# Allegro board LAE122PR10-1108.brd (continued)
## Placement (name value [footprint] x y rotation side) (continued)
PC939  -  [C_0402]  59.18 57.03 180 bottom
PC940  -  [C_0603]  40.54 70.18 90 top
PC941  -  [C_0603]  52.41 65.1 90 top
PC942  -  [C_0402]  59.16 56.14 180 bottom
PC943  -  [C_0402]  56.12 54.35 90 bottom
PC944  -  [C_0402]  54.75 52.14 0 bottom
PC945  -  [C_0402]  60.48 54.93 90 bottom
PC946  -  [C_0402]  58.95 54.35 90 bottom
PC947  -  [C_0402]  57.01 54.35 90 bottom
PC949  -  [C_0402]  45.19 56.46 180 bottom
PC950  -  [C_0402]  58.06 55.27 270 bottom
PC951  -  [C_B2]  50.21 78.18 180 bottom
PC1001  -  [C_0603]  109.43 99.96 90 top
PC1002  -  [C_0603]  110.7 99.96 90 top
PC1003  -  [C_0603]  108.16 106.18 270 top
PC1004  -  [C_0603]  109.43 103.77 270 top
PC1005  -  [C_0603]  73.81 110.82 90 bottom
PC1006  -  [C_0603]  83.02 105.74 270 bottom
PC1007  -  [C_0603]  111.97 106.18 270 top
PC1008  -  [C_0603]  73.81 110.82 90 top
PC1009  -  [C_0603]  83.02 108.6 270 bottom
PC1010  -  [C_0603]  81.81 108.6 270 bottom
PC1011  -  [C_0603]  87.84 105.74 270 top
PC1012  -  [C_0603]  75.02 110.82 90 top
PC1013  -  [C_0603]  84.22 105.74 270 top
PC1014  -  [C_0603]  100.49 106.75 270 top
PC1015  -  [C_0603]  101.69 106.75 270 top
PC1016  -  [C_0603]  102.89 106.75 270 top
PC1017  -  [C_0603]  104.08 106.75 270 top
PC1018  -  [C_0603]  105.27 106.75 270 top
PC1019  -  [C_0603]  100.47 104.26 270 top
PC1020  -  [C_0603]  101.67 104.26 270 top
PC1021  -  [C_0603]  102.86 104.26 270 top
PC1022  -  [C_0603]  104.05 104.26 270 top
PC1023  -  [C_0603]  105.25 104.26 270 top
PC1024  -  [C_0603]  99.08 101.61 270 top
PC1025  -  [C_0603]  100.35 101.61 270 top
PC1026  -  [C_0603]  101.62 101.61 270 top
PC1027  -  [C_0603]  102.89 101.61 270 top
PC1028  -  [C_0603]  104.16 101.61 270 top
PC1029  -  [C_0603]  105.43 101.61 270 top
PC1030  -  [C_0201]  114.44 106.36 0 top
PC1031  -  [C_0201]  107.2 103.82 180 top
PC1032  -  [C_0201]  114.44 102.86 0 top
PC1033  -  [C_0201]  114.44 103.44 0 top
PC1034  -  [C_0201]  114.44 104.02 0 top
PC1035  -  [C_0201]  114.44 104.61 0 top
PC1036  -  [C_0201]  114.44 105.19 0 top
PC1037  -  [C_0201]  114.44 105.78 0 top
PC1038  -  [C_0201]  107.2 102.65 180 top
PC1039  -  [C_0201]  107.2 103.24 180 top
PC1040  -  [C_0201]  98.54 109 0 top
PC1041  -  [C_0201]  104.03 108.91 0 top
PC1042  -  [C_0201]  101.5 108.62 180 top
PC1043  -  [C_0201]  94.65 101.59 180 top
PC1044  -  [C_0201]  96.33 108.21 180 top
PC1045  -  [C_0201]  99.53 106.86 270 top
PC1046  -  [C_0201]  98.96 106.86 270 top
PC1047  -  [C_0201]  97.46 99.52 0 top
PC1048  -  [C_0201]  99.58 104.46 90 top
PC1049  -  [C_0201]  98.97 104.46 90 top
PC1050  -  [C_0201]  114.49 109.08 180 top
PC1051  -  [C_0201]  112.7 108.98 0 top
PC1052  -  [C_0201]  110.87 108.98 180 top
PC1053  -  [C_0201]  109.08 108.98 0 top
PC1054  -  [C_0201]  114.44 106.94 0 top
PC1055  -  [C_0201]  99.56 103.83 270 top
PC1056  -  [C_0201]  98.95 103.85 270 top
PC1057  -  [C_0603]  118.04 99.81 180 top
PC1058  -  [C_0603]  119.01 99.81 0 top
PC1059  -  [C_0603]  117.22 107.1 180 top
PC1060  -  [C_0603]  117.75 104.63 90 top
PC1061  -  [C_0603]  76.22 110.82 90 bottom
PC1062  -  [C_D3]  73.58 107.07 180 top
PC1063  -  [C_D3]  73.3 95.01 270 top
PC1064  -  [C_0603]  89.05 105.74 270 top
PC1065  -  [C_0603]  108.16 103.77 270 top
PC1066  -  [C_0603]  113.24 103.77 270 top
PC1067  -  [C_0603]  110.7 106.18 270 top
PC1068  -  [C_0603]  111.97 103.77 270 top
PC1069  -  [C_0603]  80.61 105.74 270 bottom
PC1070  -  [C_0603]  81.81 105.74 270 bottom
PC1071  -  [C_0603]  80.61 108.6 270 bottom
PC1072  -  [C_0603]  85.43 105.74 270 top
PC1073  -  [C_0603]  110.7 103.77 270 top
PC1074  -  [C_0603]  75.02 110.82 90 bottom
PC1075  -  [C_0603]  86.64 105.74 270 top
PC1076  -  [C_0603]  111.97 99.96 90 top
PC1077  -  [C_0603]  113.24 106.18 270 top
PC1078  -  [C_0603]  109.43 106.18 270 top
PC1079  -  [C_0603]  84.22 105.74 270 bottom
PC1080  -  [C_0603]  108.16 98.82 180 top
PC1081  -  [C_0603]  108.16 99.96 90 top
PC1082  -  [C_0603]  113.24 99.96 90 top
PC1083  -  [C_0201]  107.2 108.49 180 top
PC1084  -  [C_0201]  111.49 108.98 0 top
PC1085  -  [C_0201]  111.39 110.12 0 top
PC1086  -  [C_0201]  107.2 107.91 180 top
PC1087  -  [C_0201]  107.2 107.33 180 top
PC1088  -  [C_0201]  107.2 106.74 180 top
PC1089  -  [C_0201]  107.2 106.16 180 top
PC1090  -  [C_0201]  107.2 105.57 180 top
PC1091  -  [C_0201]  107.2 104.99 180 top
PC1092  -  [C_0201]  107.2 104.4 180 top
PC1093  -  [C_0201]  114.44 102.27 0 top
PC1094  -  [C_0201]  114.44 101.69 0 top
PC1095  -  [C_0201]  114.44 101.1 0 top
PC1096  -  [C_0201]  114.44 100.52 0 top
PC1097  -  [C_0201]  107.2 100.32 180 top
PC1098  -  [C_0201]  107.2 99.73 180 top
PC1099  -  [C_0201]  107.2 101.48 180 top
PC1125  -  [C_0201]  107.2 100.9 180 top
PC1126  -  [C_0201]  107.2 102.07 180 top
PC1127  -  [C_D2]  74.51 108.3 270 bottom
PC1128  -  [C_D2]  74.51 98.27 270 bottom
PC1129  -  [C_0603]  90.32 99.39 270 top
PC1130  -  [C_0603]  90.32 102.18 270 top
PC1131  -  [C_0603]  89.11 102.18 270 top
PC1132  -  [C_0603]  89.11 99.39 270 top
PC1133  -  [C_0603]  87.91 102.18 270 top
PC1134  -  [C_0603]  87.91 99.39 270 top
PC1135  -  [C_0603]  86.7 102.18 270 top
PC1136  -  [C_0603]  86.7 99.39 270 top
PC1137  -  [C_0603]  85.49 102.18 270 top
PC1138  -  [C_0603]  85.49 99.39 270 top
PC1139  -  [C_0603]  117.4 103.55 180 top
PC1140  -  [C_0603]  76.76 118.78 90 top
PC1141  -  [C_0603]  74.34 118.78 90 top
PC1142  -  [C_0603]  76.21 118.78 90 bottom
PC1143  -  [C_0603]  73.14 118.78 90 top
PC1144  -  [C_0603]  75 118.78 90 bottom
PC1145  -  [C_0603]  75.55 118.78 90 top
PC1146  -  [C_0603]  73.8 118.78 90 bottom
PC1147  -  [C_0201]  116.31 110.17 180 top
PC1148  -  [C_0201]  118.51 107.82 0 top
PC1149  -  [C_0201]  116.39 106.01 180 top
PC1150  -  [C_0201]  116.39 105.44 180 top
PC1151  -  [C_0201]  116.39 104.87 180 top
PC1152  -  [C_0201]  118.48 103.49 0 top
PC1153  -  [C_0201]  118.48 102.91 0 top
PC1164  -  [C_0201]  114.44 107.53 0 top
PC1170  -  [C_0603]  85.43 105.74 270 bottom
PC1171  -  [C_0603]  86.64 105.74 270 bottom
PC1172  -  [C_0603]  84.22 108.6 270 bottom
PC1173  -  [C_0603]  85.43 108.6 270 bottom
PC1174  -  [C_0603]  86.64 108.6 270 bottom
PC1175  -  [C_0603]  81.75 99.39 270 bottom
PC1176  -  [C_0603]  83.02 102.18 270 bottom
PC1177  -  [C_0603]  81.75 102.18 270 bottom
PC1178  -  [C_0603]  83.02 99.39 270 bottom
PC1179  -  [C_0603]  84.29 99.39 270 top
PC1180  -  [C_0603]  84.29 102.18 270 top
PC1181  -  [C_0603]  97.12 97.61 0 top
PC1201  -  [C_0402]  36.47 58.7 270 bottom
PC1202  -  [C_0603]  46.84 103.58 270 top
PC1203  -  [C_0402]  47.46 109.62 270 top
PC1204  -  [C_0402]  35.06 63.7 0 bottom
PC1205  -  [C_0402]  39.66 53.35 180 top
PC1206  -  [C_0402]  40.97 55.13 0 top
PC1207  -  [C_0402]  41.87 56.92 270 top
PC1208  -  [C_0402]  22.87 113.17 0 top
PC1210  -  [C_0402]  31.14 120.93 270 top
PC1211  -  [C_0402]  36.59 55.13 0 top
PC1212  -  [C_0402]  36.59 56.91 0 top
PC1213  -  [C_0402]  35.14 56.7 90 top
PC1214  -  [C_0402]  28.03 124.2 90 top
PC1216  -  [C_0402]  26.07 113.17 180 top
PC1217  -  [C_0402]  248.94 97.22 90 top
PC1286  -  [C_0402]  51.48 60.15 180 top
PD1  -  [TVNST52302AB0_SOT523-3]  166.79 64.51 45 top
PD2  -  [TVNST52302AB0_SOT523-3]  165.33 63.05 45 top
PD3  -  [DB3J315E0L_SMINI3-F2-B3]  285.9 11.88 0 top
PD4  -  [PESD5V0U2BT_SOT23-3]  39.65 127.16 180 top
PD5  -  [PDS5100H-13_POWERDI5-3]  51.08 114.01 90 bottom
PD100  -  [RB520SM-30T2R_EMD2-2]  185.44 60.88 180 bottom
PD901  -  [SDMK0340L-7-F_SOD323-2]  48.91 57.54 180 bottom
PD903  -  [RB520SM-30T2R_EMD2-2]  48.91 59.26 180 bottom
PD904  -  [SDMK0340L-7-F_SOD323-2]  48.91 60.97 180 bottom
PD905  -  [BAT54CW_SOT323-3]  42.51 57.61 0 bottom
PD1202  -  [PDS5100H-13_POWERDI5-3]  49.36 107.63 270 bottom
PD1205  -  [SDMK0340L-7-F_SOD323-2]  35.14 54.25 90 bottom
PD1801  -  [BAT54CW_SOT323-3]  37.55 58.3 270 bottom
PH601  -  [R_0402]  58.77 94.5 180 bottom
PH602  -  [R_0402]  67.35 94.63 180 bottom
PH603  -  [R_0402]  57.29 111.71 0 bottom
PH604  -  [R_0402]  72.68 119.64 270 bottom
PH605  -  [R_0402]  66.43 103.13 0 bottom
PJP1  -  [JUMP_43X39]  125.87 124.03 0 top
PJP2  -  [JUMP_43X39]  121.8 123.9 0 top
PJP3  -  [JUMP_43X118]  138.96 122.73 270 bottom
PJP4  -  [JUMP_43X39]  145.96 83.13 180 top
PJP7  -  [JUMP_43X39]  36.16 88.23 270 top
PJP8  -  [JUMP_43X118]  21.44 76.21 0 bottom
PJP13  -  [JUMP_43X39]  65.04 127.2 0 top
PJP14  -  [JUMP_43X79]  271.76 73.35 0 top
PJP15  -  [JUMP_43X39]  247.99 67.4 270 top
PJP16  -  [JUMP_43X39]  246.21 60.16 270 top
PJP17  -  [JUMP_43X79]  243.17 59.68 270 top
PJP18  -  [JUMP_43X39]  245.77 66.48 90 top
PJP19  -  [JUMP_43X39]  265.89 57.54 0 top
PJP20  -  [JUMP_43X39]  262.37 87.12 90 top
PJP21  -  [JUMP_43X39]  259.99 87.12 90 top
PJP22  -  [JUMP_43X39]  251.46 76.13 90 top
PJP31  -  [JUMP_43X118]  27.27 49.25 90 bottom
PJP35  -  [JUMP_43X39]  206.58 56.4 0 top
PJP36  -  [JUMP_43X79]  249.39 108.38 270 top
PJP37  -  [JUMP_43X39]  248.7 113.36 180 top
PJP38  -  [JUMP_43X39]  149.68 65.42 180 top
PJP39  -  [JUMP_43X118]  153 65.31 90 top
PJP40  -  [JUMP_43X79]  276.1 86.05 180 top
PJP41  -  [JUMP_43X118]  276.67 95.9 180 top
PJP42  -  [JUMP_43X39]  211.59 51.45 0 top
PJP100  -  [JUMP_43X79]  152.49 67.34 90 bottom
PJP101  -  [JUMP_43X79]  182.9 50.77 90 bottom
PJP102  -  [JUMP_43X118]  167.73 72.19 270 bottom
PJP103  -  [JUMP_43X118]  198.67 55.95 0 top
PJP200  -  [JUMP_43X118]  71.8 58.43 0 top
PJP201  -  [JUMP_43X39]  70.81 70.89 0 top
PJP202  -  [JUMP_43X79]  63.48 75.19 0 top
PJP301  -  [JUMP_43X79]  147.98 82.62 90 bottom
PJP302  -  [JUMP_43X118]  160.4 87.86 180 bottom
PJP391  -  [JUMP_43X39]  152.17 109.5 0 bottom
PJP401  -  [JUMP_43X79]  137.25 128.2 270 bottom
PJP402  -  [JUMP_43X79]  149.25 125.72 270 bottom
PJP403  -  [JUMP_43X39]  145.79 128.53 180 bottom
PJP404  -  [JUMP_43X39]  161.82 127.11 180 bottom
PJP501  -  [JUMP_43X39]  168.19 68.46 315 bottom
PJP502  -  [JUMP_43X39]  177.63 61.48 315 bottom
PJP505  -  [JUMP_43X39]  153.9 57.61 180 top
PJP506  -  [JUMP_43X39]  146.66 62.43 180 top
PJP601  -  [JUMP_43X118]  61.43 82.86 270 bottom
PJP602  -  [JUMP_43X79]  65.05 88.19 270 top
PJP603  -  [JUMP_43X39]  64.22 113.31 270 bottom
PJP901  -  [JUMP_43X118-NPM]  49.6 83.01 180 bottom
PJP1202  -  [JUMP_43X118]  29.45 115.45 0 top
PJPDC1  -  [CVILU_CI0805M1HRC-NH_5P-T]  38 122.55 270 bottom
PL1  -  [TAIYO_FBMJ4516HS720NT_2P]  171.16 54.93 90 top
PL2  -  [TAIYO_FBMJ4516HS720NT_2P]  173.44 54.93 90 top
PL3  -  [MURAT_BLM15AG102SN1D_2P]  37.93 123.35 0 top
PL4  -  [TAIYO_FBMJ4516HS720NT_2P]  41.23 120.79 0 bottom
PL100  -  [CYNTE_PCMC063T-1R5MN_2P]  158.77 76.59 0 bottom
PL101  -  [CYNTE_PCMC063T-1R5MN_2P]  189.26 55.25 0 bottom
PL201  -  [CYNTE_PCMB063T-1R0MS_2P]  67.4 65.91 270 bottom
PL301  -  [MAG_MMD-05CZ-R68M-X2L_2P]  159.2 82.69 0 bottom
PL402  -  [MAG_MLV-FY12N1R0M-O1L_2P]  138.55 130.76 180 bottom
PL404  -  [MAG_MLV-FY12N1R0M-O1L_2P]  154.42 127.96 180 bottom
PL501  -  [MAG_MLV-FY12N1R0M-O1L_2P]  174.17 63.73 315 bottom
PL602  -  [9A_Z80_1812_2P-NPM]  61.43 84.21 270 bottom
PL610  -  [MAG_MMD06CZER15MG_4P]  69.94 107.39 180 bottom
PL612  -  [MAG_MMD06CZER15MG_4P]  70.25 98.88 180 bottom
PL614  -  [MAG_MMD05CZR47M_4P]  75.21 115.5 180 bottom
PL901  -  [MAGLA_MMD-05CZ-1R0M-M7L_2P]  47 83.01 0 bottom
PL902  -  [CYNTE_PCMB103T-2R2MS_2P]  44.19 68.02 0 bottom
PL1201  -  [5A_Z120_0805_2P]  23.53 116.22 0 top
PL1202  -  [5A_Z120_0805_2P]  23.53 114.56 0 top
PQ1  -  [DMN65D8LDW-7_SOT363-6]  55.39 112.33 90 top
PQ2  -  [FDV301N-G_SOT23-3]  37.2 121.91 90 top
PQ3  -  [MMST3904-7-F_SOT323-3]  35.46 124.92 0 top
PQ4  -  [FDMC6679AZ_MLP8-5]  47.73 112.05 180 bottom
PQ5  -  [NTR4502PT1G_SOT23-3]  48.51 113.74 270 top
PQ6  -  [DMN65D8LW-7_SOT323-3]  49.68 120.47 270 bottom
PQ7  -  [DMN65D8LW-7_SOT323-3]  44.03 111.87 90 bottom
PQ8  -  [DMN65D8LW-7_SOT323-3]  59.14 119.84 270 bottom
PQ9  -  [FDMC6679AZ_MLP8-5]  45.78 118.76 0 bottom
PQ501  -  [AON7934_DFN3X3A8-10]  68.05 113.57 180 bottom
PQ904  -  [AON6970_DFN5X6D-8-7]  59.88 65.42 90 top
PQ905  -  [AON6992_DFN5X6D-8-7]  47.78 71.49 90 top
PQ906  -  [AON7409_DFN8-5]  175.56 54.14 0 top
PQ909  -  [DMN65D8LW-7_SOT323-3]  51.2 54.31 0 bottom
PQ1201  -  [DMN65D8LDW-7_SOT363-6]  46.44 106.29 90 top
PQ1202  -  [FDMC6679AZ_MLP8-5]  51.61 109.55 180 top
PQ1203  -  [NTR4502PT1G_SOT23-3]  44.54 105.14 180 bottom
PQ1204  -  [DMN65D8LDW-7_SOT363-6]  40.59 107.01 0 bottom
PQ1205  -  [DMN65D8LW-7_SOT323-3]  40.73 63.7 180 bottom
PQ1206  -  [FDMC6679AZ_MLP8-5]  30.06 119.05 90 top
PQ1207  -  [DMN66D0LDW-7_SOT363-6]  44.29 50.48 90 bottom
PQ1208  -  [DMN66D0LDW-7_SOT363-6]  41.02 50.48 90 bottom
PQ1209  -  [DMN65D8LDW-7_SOT363-6]  30.95 123.57 90 top
PQ1210  -  [DMN66D0LDW-7_SOT363-6]  52.66 51.78 270 bottom
PQ1211  -  [DMN66D0LDW-7_SOT363-6]  49.42 51.78 270 bottom
PQ1212  -  [DMN65D8LW-7_SOT323-3]  33.7 58.13 0 bottom
PQ1213  -  [FDMC6679AZ_MLP8-5]  48.53 105.19 270 top
PQ1214  -  [DMN65D8LDW-7_SOT363-6]  44.69 101.02 270 top
PQ1215  -  [NTR4502PT1G_SOT23-3]  46.46 101.71 270 bottom
PQ1216  -  [DMN65D8LW-7_SOT323-3]  59.68 51.32 270 bottom
PR1  -  [R_0402]  168.17 65.23 315 top
PR2  -  [R_0402]  283.93 9.9 90 top
PR3  -  [R_0402]  42.31 120.61 270 top
PR4  -  [R_0402]  44.09 120.61 270 top
PR5  -  [R_0402]  43.2 119.7 90 top
PR6  -  [R_0402]  37.17 125.63 270 top
PR7  -  [R_0402]  33.74 126.2 270 top
PR8  -  [R_0402]  37.17 127.4 270 top
PR10  -  [R_0402]  52.35 114.96 270 top
PR11  -  [R_0402]  46.33 109.8 180 bottom
PR12  -  [R_0402]  46.62 121.55 0 bottom
PR13  -  [R_0805]  43.78 118.97 270 bottom
PR14  -  [R_0402]  44.42 116.03 180 bottom
PR15  -  [R_0402]  52.35 113.12 270 top
PR16  -  [R_0402]  44.41 109.79 90 bottom
PR17  -  [R_0402]  55.19 114.76 0 top
PR18  -  [R_0402]  48.4 121.55 0 bottom
PR19  -  [R0402_0OHM]  56.98 113.85 90 top
PR20  -  [R0402_0OHM]  42.07 110.06 180 bottom
PR21  -  [R0402_0OHM]  57.69 121.42 180 bottom
PR22  -  [R0402_0OHM]  57.69 120.53 180 bottom
PR23  -  [R0402_0OHM]  52.73 120.14 90 bottom
PR24  -  [R_0402]  41.04 111.44 90 bottom
PR25  -  [R0402_0OHM]  54.33 114.76 180 top
PR26  -  [R0402_0OHM]  60.15 118.82 0 top
PR27  -  [R_0402]  57.69 119.64 180 bottom
PR28  -  [R_0402]  61.06 119.71 180 top
PR29  -  [R0402_0OHM]  60.15 121.61 0 bottom
PR100  -  [R0603_0OHM]  156.36 72.53 270 bottom
PR102  -  [R_0402]  182.92 58.94 180 bottom
PR103  -  [R_0402]  182.92 59.83 180 bottom
PR104  -  [R0402_0OHM]  157.75 79.74 0 top
PR105  -  [R0402_0OHM]  157.75 78.85 0 top
PR106  -  [R_1206]  158.84 72.15 0 bottom
PR107  -  [R_0402]  180.82 57.59 180 bottom
PR108  -  [R_0402]  155.21 79.58 0 bottom
PR111  -  [R0603_0OHM]  186.4 52.27 270 bottom
PR112  -  [R_1206]  188.11 54.37 0 top
PR113  -  [R_0402]  181.7 57.61 270 bottom
PR114  -  [R0402_0OHM]  183.79 59.84 270 bottom
PR116  -  [R_0402]  152.55 78.8 90 bottom
PR117  -  [R_0402]  185.75 59.84 0 bottom
PR119  -  [R0402_0OHM]  179.03 57.61 270 bottom
PR120  -  [R0402_0OHM]  180.82 56.7 180 bottom
PR202  -  [R_1206]  67.65 66.37 90 top
PR203  -  [R0603_0OHM]  64.41 68.4 180 bottom
PR204  -  [R_0402]  63.96 71.7 0 top
PR205  -  [R_0402]  64.48 71.65 270 bottom
PR206  -  [R_0402]  64.87 72.59 180 top
PR207  -  [R_0402]  63.59 70.74 90 bottom
PR208  -  [R0402_0OHM]  70.9 74.13 180 top
PR209  -  [R_0402]  70.89 75 90 top
PR210  -  [R0402_0OHM]  72.68 74.13 180 top
PR212  -  [R_0402]  71.78 75 90 top
PR302  -  [R_0402]  156.11 86.17 90 bottom
PR303  -  [R_1206]  159.47 83.69 270 top
PR304  -  [R0603_0OHM]  156.42 83.83 0 top
PR306  -  [R_0402]  154.33 87.08 270 bottom
PR307  -  [R_0402]  157.1 86.19 180 top
PR308  -  [R_0402]  153.44 87.08 270 bottom
PR310  -  [R_0402]  156.18 87.04 90 top
PR311  -  [R_0402]  155.22 86.17 90 bottom
PR312  -  [R0402_0OHM]  157 86.17 90 bottom
PR402  -  [R0402_0OHM]  144.68 128.14 90 top
PR403  -  [R_0402]  143.72 128.14 90 top
PR404  -  [R_0402]  140.36 129.82 270 top
PR405  -  [R_0603]  138.52 131.52 270 top
PR406  -  [R0402_0OHM]  164.63 127.52 180 top
PR407  -  [R_0402]  163.71 126.63 0 top
PR408  -  [R_0402]  157 131.09 270 top
PR409  -  [R_0603]  154.33 128.66 270 top
PR410  -  [R_0402]  164.63 129.3 180 top
PR411  -  [R_0402]  159.93 132.09 180 bottom
PR412  -  [R_0402]  137.68 133.36 0 bottom
PR413  -  [R_0402]  143.99 133.74 180 bottom
PR414  -  [R_0402]  142.2 133.75 270 top
PR415  -  [R_0402]  143.08 132.85 0 bottom
PR416  -  [R_0402]  143.08 132.85 0 top
PR417  -  [R_0402]  159.03 133.88 270 bottom
PR418  -  [R_0402]  157.88 131.09 270 top
PR419  -  [R_0402]  159.02 131.2 0 bottom
PR420  -  [R_0402]  158.77 130.17 90 top
PR421  -  [R_0402]  139.52 132.66 0 bottom
PR422  -  [R_0402]  140.44 133.55 180 bottom
PR423  -  [R0402_0OHM]  156.37 132.09 180 bottom
PR424  -  [R_0402]  156.37 131.2 180 bottom
PR425  -  [R0402_0OHM]  140.35 128.03 0 top
PR426  -  [R0402_0OHM]  164.63 128.41 180 top
PR427  -  [R_0402]  142.21 132.85 180 bottom
PR428  -  [R_0402]  158.15 131.2 180 bottom
PR501  -  [R_0402]  172.91 68.27 135 bottom
PR502  -  [R_0603]  172.63 62.31 135 bottom
PR504  -  [R0402_0OHM]  174.55 68.19 225 bottom
PR505  -  [R_0402]  174.53 66.91 45 bottom
PR506  -  [R_0402]  172.28 70.16 225 bottom
PR513  -  [R0402_0OHM]  149.38 57.49 270 top
PR514  -  [R_0402]  151.15 56.58 90 top
PR515  -  [R_0402]  146.96 60.86 270 top
PR516  -  [R_0402]  146.06 59.07 0 top
PR517  -  [R_0402]  171.06 67.91 135 bottom
PR601  -  [R_0402]  44.99 93.74 180 bottom
PR602  -  [R0402_0OHM]  44.99 96.59 180 top
PR603  -  [R0402_0OHM]  44.99 97.48 180 top
PR604  -  [R_0402]  44.99 94.63 180 bottom
PR605  -  [R_0402]  44.99 95.51 180 bottom
PR606  -  [R0402_0OHM]  58.63 114.55 180 bottom
PR608  -  [R_0402]  47.06 95.45 0 bottom
PR610  -  [R_0402]  47.57 89.8 0 top
PR611  -  [R_0402]  47.27 97.24 270 bottom
PR612  -  [R_0402]  44.33 92.53 0 top
PR613  -  [R_0402]  46.51 92.04 270 bottom
PR614  -  [R0402_0OHM]  44.85 90.04 90 top
PR616  -  [R0402_0OHM]  45.74 90.04 90 top
PR617  -  [R_0402]  50.07 91.58 180 bottom
PR618  -  [R_0402]  44.46 93.42 0 top
PR619  -  [R_0603]  61.17 112.91 0 top
PR620  -  [R0402_0OHM]  46.63 88.9 90 top
PR621  -  [R_0402]  49.36 88.01 90 top
PR622  -  [R_0402]  50.27 89.8 180 top
PR623  -  [R_0402]  48.4 88.02 90 top
PR624  -  [R_0603]  71.4 115.71 180 top
PR625  -  [R0402_0OHM]  44.46 94.31 0 top
PR626  -  [R_0402]  44.46 95.2 0 top
PR627  -  [R_1206]  68.79 114.5 180 top
PR628  -  [R_0402]  67.33 97.5 270 top
PR629  -  [R_0402]  50.87 93.42 0 bottom
PR630  -  [R_0402]  49.12 97.23 180 bottom
PR631  -  [R_0402]  48.28 92.04 270 bottom
PR632  -  [R_0402]  53.82 88.85 180 top
PR633  -  [R_0402]  66.44 97.5 270 top
PR635  -  [R_0402]  54.51 91.88 90 top
PR636  -  [R_0402]  48.98 99.38 90 bottom
PR638  -  [R_0402]  53.82 89.74 180 top
PR639  -  [R_0402]  52.67 95.46 270 bottom
PR640  -  [R_0402]  55.38 97.23 0 top
PR641  -  [R_0402]  47.19 100.28 0 bottom
PR642  -  [R_0402]  71.73 118.73 90 bottom
PR643  -  [R_0402]  71.16 116.79 180 top
PR644  -  [R_0402]  55.38 98.12 0 top
PR645  -  [R_0402]  56.3 93.67 180 top
PR646  -  [R_0402]  50.76 99.38 90 bottom
PR647  -  [R_0402]  51.89 91.9 0 bottom
PR648  -  [R_0402]  54.51 94.58 270 top
PR649  -  [R_0402]  51.64 99.39 0 bottom
PR650  -  [R_0402]  55.38 92.78 0 top
PR651  -  [R_0402]  50.89 97.24 270 bottom
PR652  -  [R_0402]  49.87 99.38 90 bottom
PR656  -  [R_0402]  64.02 105.23 0 top
PR657  -  [R_0402]  64.65 103.13 0 bottom
PR659  -  [R0402_0OHM]  59.98 111.71 180 bottom
PR660  -  [R_0603]  52.22 109.42 0 bottom
PR661  -  [R_0603]  64.92 106.31 180 top
PR662  -  [R_0402]  55.13 111.71 0 bottom
PR663  -  [R_1206]  61.61 102.37 180 bottom
PR671  -  [R0402_0OHM]  59.6 95.51 180 bottom
PR672  -  [R_0603]  60.55 87.65 90 bottom
PR674  -  [R_0603]  65.3 97.48 90 top
PR676  -  [R_1206]  62.38 98.05 270 top
PR678  -  [R_0402]  47.08 93.66 90 bottom
PR679  -  [R0402_0OHM]  61 116.09 180 top
PR680  -  [R_0402]  59.26 90.88 0 top
PR901  -  [R_1206_4P-D]  48.27 83.28 0 top
PR909  -  [R_0402]  53.48 60.97 0 bottom
PR910  -  [R_0402]  53.48 61.86 0 bottom
PR914  -  [R0603_0OHM]  57.05 61.22 90 top
PR915  -  [R_0402]  60.91 59.26 0 top
PR916  -  [R_0805]  53.26 59.45 180 bottom
PR917  -  [R_1206_4P-D]  170.08 52.03 0 top
PR918  -  [R_0402]  52.98 56.58 90 bottom
PR919  -  [R_0402]  50.56 58.37 0 top
PR920  -  [R0402_0OHM]  50.56 57.48 0 top
PR921  -  [R_0603]  60.79 58.05 0 top
PR922  -  [R0402_0OHM]  50.56 56.59 0 top
PR923  -  [R_1206]  43.52 68.65 180 top
PR924  -  [R_1206]  55.71 63.57 180 top
PR925  -  [R_0402]  53.85 56.45 0 bottom
PR926  -  [R0402_0OHM]  50.56 55.7 0 top
PR927  -  [R_0402]  50.81 57.29 0 bottom
PR928  -  [R0402_0OHM]  52.98 55.71 270 bottom
PR929  -  [R0402_0OHM]  60.84 56.78 0 bottom
PR930  -  [R_0402]  53.85 55.56 0 bottom
PR931  -  [R_0402]  53.94 52.07 90 top
PR932  -  [R_0402]  55.71 52.98 270 top
PR933  -  [R_0402]  54.82 52.07 90 top
PR934  -  [R_0402]  55.66 53.03 180 bottom
PR935  -  [R0402_0OHM]  56.59 50.75 0 top
PR936  -  [R0402_0OHM]  57.49 52.98 270 top
PR937  -  [R_0402]  61.35 55.83 0 bottom
PR938  -  [R_0402]  61.35 54.94 0 bottom
PR939  -  [R0402_0OHM]  44.22 58.61 90 bottom
PR940  -  [R_0402]  58.38 52.07 90 top
PR941  -  [R0402_0OHM]  40.73 58.61 90 bottom
PR942  -  [R0402_0OHM]  48.26 54.75 180 bottom
PR943  -  [R0603_0OHM]  53.11 60.59 0 top
PR944  -  [R_0402]  51.5 62.14 180 top
PR945  -  [R_0402]  51.48 61.06 180 top
PR946  -  [R0402_0OHM]  43.27 54.1 90 bottom
PR947  -  [R0402_0OHM]  56.59 52.14 0 bottom
PR948  -  [R_0402]  57.61 53.03 0 bottom
PR949  -  [R0402_0OHM]  56.6 52.98 270 top
PR950  -  [R_0402]  45.11 59.52 270 bottom
PR951  -  [R0402_0OHM]  52.91 52.84 0 bottom
PR953  -  [R_0402]  43.46 56.16 270 top
PR960  -  [R0402_0OHM]  50.56 59.26 0 top
PR1201  -  [R_0402]  41.88 53.35 180 top
PR1202  -  [R_0402]  44.3 108.91 180 bottom
PR1203  -  [R_0402]  40.98 56.01 90 top
PR1205  -  [R_0402]  45.74 103.21 270 top
PR1206  -  [R_0402]  38.75 56.02 0 top
PR1207  -  [R_0402]  48.35 109.62 270 top
PR1208  -  [R_0402]  38.75 55.13 0 top
PR1209  -  [R_0402]  42.06 108.93 270 bottom
PR1210  -  [R_0402]  33.29 54.43 0 top
PR1211  -  [R0402_0OHM]  36.52 62.56 0 top
PR1212  -  [R_0402]  44.85 102.3 90 top
PR1213  -  [R_0402]  48.36 107.83 180 top
PR1214  -  [R_0402]  41.54 102.97 180 bottom
PR1215  -  [R0402_0OHM]  37.76 63.7 180 bottom
PR1216  -  [R0402_0OHM]  36.36 60.23 180 bottom
PR1217  -  [R_0402]  39.66 54.24 180 top
PR1218  -  [R0402_0OHM]  41.54 103.86 180 bottom
PR1219  -  [R_0402]  40.97 54.24 0 top
PR1220  -  [R0402_0OHM]  42.68 106.94 0 top
PR1221  -  [R0402_0OHM]  41.63 60.65 180 bottom
PR1222  -  [R_0402]  42.68 107.83 0 top
PR1223  -  [R0402_0OHM]  41.17 108.01 90 bottom
PR1224  -  [R_0402]  39.79 60.65 180 bottom
PR1225  -  [R0402_0OHM]  38.95 61.59 90 bottom
PR1226  -  [R_0402]  36.84 64.59 0 bottom
PR1227  -  [R_0402]  27.85 122.44 180 top
PR1228  -  [R_0402]  32.03 120.01 90 top
PR1229  -  [R_0402]  29.69 122.44 180 top
PR1230  -  [R_0402]  46.19 51.18 90 top
PR1231  -  [R_0402]  50.06 51.18 90 top
PR1232  -  [R_0402]  44.73 51.18 90 top
PR1233  -  [R_0402]  47.08 51.18 90 top
PR1234  -  [R_0402]  43.84 50.54 90 top
PR1235  -  [R_0402]  49.16 52.84 0 bottom
PR1236  -  [R_0402]  30.94 125.99 0 top
PR1237  -  [R_0402]  37.5 57.8 180 top
PR1238  -  [R0402_0OHM]  35.14 54.93 90 top
PR1239  -  [R_0402]  37.5 53.35 180 top
PR1240  -  [R_0402]  34.25 57.62 270 top
PR1241  -  [R0402_0OHM]  44.74 52.84 180 bottom
PR1242  -  [R0402_0OHM]  47.97 52.09 270 top
PR1243  -  [R0402_0OHM]  33.36 56.7 90 top
PR1244  -  [R0402_0OHM]  40.71 52.02 0 top
PR1245  -  [R0402_0OHM]  51.07 52.84 0 bottom
PR1246  -  [R_0402]  36.59 54.24 0 top
PR1247  -  [R_0402]  36.59 56.02 0 top
PR1248  -  [R_0402]  32.41 56.7 90 top
PR1249  -  [R_0402]  33.29 55.32 0 top
PR1250  -  [R0402_0OHM]  32.41 55.33 270 top
PR1251  -  [R_0402]  52.08 101.93 180 top
PR1252  -  [R_0402]  49.95 101.93 180 top
PR1253  -  [R_0402]  45.57 98.63 180 top
PR1254  -  [R_0402]  34.25 59.4 270 top
PR1255  -  [R_0402]  32.87 56.88 0 bottom
PR1257  -  [R0402_0OHM]  47.38 52.84 0 bottom
PR1258  -  [R_0402]  45.6 52.84 0 bottom
PR1259  -  [R_0402]  41.54 52.84 0 bottom
PR1260  -  [R_0402]  40.71 51.13 0 top
PR1261  -  [R_0402]  42.95 51.46 270 top
PRP1  -  [RP_0804_8P4R]  167.81 61.67 45 top
PT1  -  [TPC12]  32.41 58.57 0 top
PU1  -  [TC7SH08FU_SSOP5]  55.71 121.18 270 bottom
PU2  -  [AP2204RA-3P3TRG1_SOT89-3]  68.22 121.02 270 bottom
PU100  -  [SY8288BRAC_QFN20_3X3]  155.36 73.9 90 bottom
PU102  -  [SY8288CRAC_QFN20_3X3]  185.84 54.09 90 bottom
PU200  -  [SY8210AQVC_QFN19_4X3]  69.06 72.01 180 bottom
PU301  -  [SYX196DQNC_QFN10_3X3]  156.53 84.67 180 bottom
PU401  -  [SY8057QDC_QFN16_3X3]  140.08 129.05 0 bottom
PU402  -  [SY8057QDC_QFN16_3X3]  155.95 127.53 0 bottom
PU501  -  [RT8097ALGE_SOT23-6]  173.97 65.51 225 bottom
PU503  -  [AP7361C-FGE-7_U-DFN3030-8_3X3]  148.3 60.61 270 top
PU602  -  [ISL62883CHRTZ-T_TQFN40_5X5-S]  48.33 91.69 0 top
PU610  -  [CSD97374CQ4M_SON8_3P5X4P5]  58.61 110.32 270 bottom
PU612  -  [CSD97374CQ4M_SON8_3P5X4P5]  60.1 94.15 0 bottom
PU614  -  [ISL95808HRZ-TS2378_DFN8_2X2-S]  60.01 113.56 90 bottom
PU901  -  [ISL88738HRTZ-T_TQFN32_4X4]  58.57 55.64 180 top
PU903  -  [TC7SH08FU_SSOP5]  46.25 55.4 270 bottom
PU1200  -  [TC7SH08FU_SSOP5]  37.51 62.6 270 bottom
PU1201  -  [LM393DGKR_VSSOP8]  41.44 56.04 180 bottom
QC2  -  [DMN65D8LDW-7_SOT363-6]  150.96 109.75 270 bottom
QE2  -  [DMN65D8LDW-7_SOT363-6]  238.86 83.83 180 bottom
QE3  -  [MMBT3904WT1G_SC70-3]  117.93 101.69 90 top
QE4  -  [MMBT3904WT1G_SC70-3]  265.9 101.86 90 top
QE5  -  [MMBT3904WT1G_SC70-3]  235.99 79.39 90 top
QE6  -  [MMBT3904WT1G_SC70-3]  55.31 100.42 90 bottom
QE7  -  [MMBT3904WT1G_SC70-3]  149.57 59.52 0 bottom
QE11  -  [L2N7002WT1G_SC-70-3]  258.92 102.69 90 top
QE12  -  [L2N7002WT1G_SC-70-3]  245.9 102.81 0 top
QE13  -  [DMN65D8LDW-7_SOT363-6]  240.29 132.13 270 bottom
QL1  -  [DMN65D8LDW-7_SOT363-6]  257.79 131.2 180 bottom
QL2  -  [DMN65D8LDW-7_SOT363-6]  260.64 131.2 180 bottom
QR1  -  [L2N7002WT1G_SC-70-3]  279.87 58.56 90 top
QT1  -  [DMN66D0LDW-7_SOT363-6]  40.47 81.69 270 bottom
QV1  -  [AO6405_TSOP6]  46.25 125.07 180 top
QV2  -  [L2N7002WT1G_SC-70-3]  40.47 123.13 0 top
QV3  -  [DMN65D8LDW-7_SOT363-6]  18.11 88.21 0 top
QV4  -  [L2N7002WT1G_SC-70-3]  17.87 78.81 90 top
QV5  -  [L2N7002WT1G_SC-70-3]  22.31 88.28 0 bottom
QV7  -  [L2N7002WT1G_SC-70-3]  48.6 122.17 0 top
QV8  -  [LP2301ALT1G_SOT23-3]  49.17 126.15 180 top
QZ1  -  [LP2301ALT1G_SOT23-3]  57.16 125.77 180 top
QZ2  -  [DMN65D8LDW-7_SOT363-6]  270.98 84.54 270 top
QZ3  -  [DDTA114EUA-7-F_SOT323-3]  285.84 11.35 0 bottom
QZ7  -  [DMN65D8LDW-7_SOT363-6]  268.56 82.23 90 top
QZ9  -  [LP2301ALT1G_SOT23-3]  153.63 103.57 180 bottom
R274  -  [R0603_0OHM]  274.85 72.74 270 top
RA3  -  [R0603_0OHM]  263.29 55.76 0 top
RA5  -  [R_0402]  250.9 61.86 0 top
RA6  -  [R_0402]  250.9 60.97 0 top
RA7  -  [R_0402]  258.34 55.01 270 top
RA8  -  [R_0402]  259.23 55.01 270 top
RA9  -  [R_0402]  256.56 66.38 270 top
RA12  -  [R_0402]  252.3 66.46 0 top
RA13  -  [R_0402]  251.43 66.46 180 top
RA14  -  [R_0402]  258.6 66.38 270 top
RA17  -  [R_0402]  257.71 65.47 90 top
RA18  -  [R_0402]  262.99 67.45 180 top
RA35  -  [R0402_0OHM]  251.37 53.03 180 top
RA36  -  [R0402_0OHM]  251.37 52.14 180 top
RA37  -  [R0402_0OHM]  250.1 59.95 180 top
RA38  -  [R0402_0OHM]  281.75 46.79 90 top
RA39  -  [R0402_0OHM]  282.45 31.54 225 top
RA44  -  [R_0402]  254.47 55.01 270 top
RA45  -  [R_0402]  251.43 65.57 180 top
RA48  -  [R0402_0OHM]  261.77 69.49 270 top
RA50  -  [R_0402]  260.88 69.49 270 top
RA51  -  [R_0402]  252.3 65.57 0 top
RA52  -  [R_0402]  259.55 66.38 270 top
RA53  -  [R_0402]  250.1 58.18 180 top
RA54  -  [R0402_0OHM]  250.1 59.07 180 top
RA55  -  [R0402_0OHM]  281.32 36.9 0 top
RA56  -  [R0402_0OHM]  281.32 35.7 0 top
RA57  -  [R_0402]  257.45 55.01 270 top
RA58  -  [R_0402]  256.56 55.01 270 top
RA59  -  [R_0402]  251.98 69.16 0 top
RA60  -  [R_0402]  253.76 69.16 0 top
RA61  -  [R_0402]  252.25 68.22 270 top
RC1  -  [R_0402]  126.82 106.4 270 top
RC2  -  [R_0402]  102.8 109.98 270 top
RC3  -  [R_0402]  125.82 120.52 90 top
RC4  -  [R_0402]  137.25 94.74 90 bottom
RC5  -  [R_0402]  120.74 84.48 270 top
RC6  -  [R_0402]  122.01 84.48 270 top
RC7  -  [R_0402]  122.9 84.48 270 top
RC10  -  [R_0402]  148.99 100.35 270 top
RC11  -  [R_0402]  148.99 92.16 270 bottom
RC12  -  [R_0402]  134.52 104.84 90 top
RC13  -  [R_0402]  136.61 81.28 90 top
RC14  -  [R_0402]  135.41 104.84 270 top
RC15  -  [R_0402]  142.19 105.93 0 bottom
RC16  -  [R_0402]  148.92 90.24 0 bottom
RC17  -  [R_0402]  142.19 106.82 0 bottom
RC19  -  [R_0402]  142.57 102.37 0 bottom
RC20  -  [R_0402]  142.19 103.26 0 bottom
RC21  -  [R_0402]  144.22 84.72 0 top
RC22  -  [R_0402]  137.5 84.48 270 top
RC23  -  [R_0402]  132.35 105.67 0 top
RC25  -  [R_0402]  142.19 105.04 0 bottom
RC27  -  [R_0402]  136.61 84.48 270 top
RC28  -  [R_0402]  156.61 100.71 90 top
RC29  -  [R_0402]  157.06 92.86 270 top
RC30  -  [R_0402]  160.49 96.42 270 top
RC31  -  [R_0402]  160.49 93.6 90 top
RC32  -  [R_0402]  163.74 102.5 180 bottom
RC33  -  [R0402_0OHM]  162.83 100.47 0 bottom
RC34  -  [R0402_0OHM]  162.83 99.39 0 bottom
RC35  -  [R0402_0OHM]  163.74 97.93 180 bottom
RC36  -  [R0402_0OHM]  163.74 95.83 180 bottom
RC37  -  [R0402_0OHM]  163.74 96.72 180 bottom
RC38  -  [R0402_0OHM]  163.66 93.91 90 bottom
RC39  -  [R_0402]  161.38 96.42 270 top
RC40  -  [R0402_0OHM]  163.66 92.07 90 bottom
RC41  -  [R0402_0OHM]  149.95 101.22 90 top
RC42  -  [R_0402]  163.74 101.61 180 bottom
RC43  -  [R_0402]  161.39 97.29 180 top
RC44  -  [R_0402]  130.62 101.84 90 top
RC45  -  [R_0402]  130 109.68 0 top
RC46  -  [R_0402]  114.31 118.21 0 bottom
RC47  -  [R_0402]  144.75 96.53 180 bottom
RC48  -  [R_0402]  124.31 82.69 180 top
RC50  -  [R_0402]  144.75 95.64 180 bottom
RC51  -  [R_0402]  144.75 98.31 180 bottom
RC52  -  [R_0402]  118.77 105.55 0 top
RC54  -  [R_0402]  133.87 82.62 0 top
RC56  -  [R_0402]  130.77 82.26 270 top
RC57  -  [R_0402]  127.42 82.69 180 top
RC59  -  [R_0402]  138.82 83.58 0 top
RC60  -  [R_0402]  157.81 118.57 0 bottom
RC62  -  [R0402_0OHM]  157.81 119.45 0 bottom
RC65  -  [R_0402]  155.33 117.42 0 bottom
RC67  -  [R_0402]  136.61 79.44 90 top
RC68  -  [R_0402]  141.62 81.29 0 top
RC69  -  [R_0402]  127.42 83.58 180 top
RC71  -  [R_0402]  90.89 120.65 90 bottom
RC72  -  [R_0402]  131.02 84.48 270 top
RC73  -  [R_0402]  141.57 84.86 270 top
RC74  -  [R_0402]  143.34 84.86 270 top
RC75  -  [R_0402]  126.71 81.43 270 top
RC77  -  [R_0402]  85.37 121.56 270 bottom
RC78  -  [R_0402]  90.89 119.78 270 bottom
RC79  -  [R_0402]  96.29 119.76 90 bottom
RC80  -  [R_0402]  95.41 120.66 180 bottom
RC81  -  [R_0402]  99.02 121.09 90 bottom
RC82  -  [R_0402]  99.91 121.09 90 bottom
RC83  -  [R_0402]  89.11 120.65 90 bottom
RC84  -  [R_0402]  88.23 119.78 270 bottom
RC86  -  [R_0402]  97.29 120.53 0 top
RC87  -  [R_0402]  98.07 119.76 90 bottom
RC88  -  [R_0402]  123.79 84.48 270 top
RC89  -  [R_0402]  125.12 84.48 270 top
RC90  -  [R_0402]  92.71 109.36 180 top
RC91  -  [R_0402]  92.71 108.47 180 top
RC92  -  [R_0402]  119.98 79.87 90 top
RC93  -  [R_0402]  119.09 79.87 90 top
RC94  -  [R_0402]  124.13 77.63 180 top
RC95  -  [R_0402]  122.32 76.78 90 top
RC96  -  [R_0402]  131.52 103.26 270 top
RC109  -  [R_0402]  84.48 118.87 90 bottom
RC110  -  [R_0402]  87.21 118.87 90 bottom
RC112  -  [R_0402]  86.32 118.87 90 bottom
RC113  -  [R_0402]  87.22 120.66 180 bottom
RC114  -  [R_0402]  97.69 110.09 180 top
RC115  -  [R_0402]  89.04 133.17 0 top
RC120  -  [R_0402]  91.78 118.87 90 bottom
RC121  -  [R_0402]  99.02 127.13 90 bottom
RC122  -  [R_0402]  98.13 127.13 90 bottom
RC123  -  [R_0402]  90 120.65 90 bottom
RC124  -  [R_0402]  124.93 81.43 270 top
RC126  -  [R_0402]  90.26 126.24 90 bottom
RC128  -  [R_0402]  88.48 126.24 90 bottom
RC129  -  [R_0402]  89.37 126.24 90 bottom
RC130  -  [R_0402]  99.08 120.52 90 top
RC131  -  [R_0402]  78.38 122.58 270 bottom
RC132  -  [R_0402]  92.04 127.15 270 bottom
RC133  -  [R_0402]  148.99 101.22 90 top
RC134  -  [R_0402]  79.78 119.78 270 bottom
RC135  -  [R_0402]  82 119.78 270 bottom
RC136  -  [R_0402]  81.8 125.3 0 bottom
RC137  -  [R_0402]  88.17 133.17 180 top
RC138  -  [R_0402]  102.89 127.98 270 bottom
RC139  -  [R_0402]  86.69 128.03 0 bottom
RC140  -  [R_0402]  110.08 120.53 180 top
RC141  -  [R_0402]  110.95 120.53 0 top
RC143  -  [R0603_0OHM]  118.64 108.72 180 top
RC152  -  [R_0402]  93.57 120.66 180 bottom
RC153  -  [R_0402]  93.56 118.87 90 bottom
RC157  -  [R_0402]  92.67 118.87 90 bottom
RC161  -  [R_0402]  88.47 107.39 0 top
RC163  -  [R_0402]  88.47 108.28 0 top
RC165  -  [R_0402]  117.64 96.89 135 top
RC166  -  [R_0402]  117.75 120.46 90 top
RC167  -  [R_0402]  118.76 97.22 135 top
RC168  -  [R_0402]  116.86 121.37 270 top
RC169  -  [R0603_0OHM]  130.83 124.72 270 bottom
RC170  -  [R0402_0OHM]  126.76 125.75 270 bottom
RC171  -  [R0402_0OHM]  127.65 125.75 270 bottom
RC173  -  [R0402_0OHM]  124.17 125.75 270 bottom
RC175  -  [R_0402]  132.03 109.94 0 top
RC176  -  [R_0402]  148.99 113.31 270 top
RC177  -  [R_0402]  148.99 114.17 90 top
RC178  -  [R_0402]  132.03 109.05 0 top
RC183  -  [R_0402]  140.68 84.86 270 top
RC184  -  [R_0402]  140.1 97.98 90 top
RC186  -  [R_0402]  134.83 84.48 270 top
RC187  -  [R_0402]  123.21 79.36 0 top
RC189  -  [R_0402]  144.75 97.42 180 bottom
RC190  -  [R_0402]  138.82 82.69 0 top
RC211  -  [R_0402]  145.05 81.54 0 top
RC212  -  [R0402_0OHM]  147.74 81.54 180 top
RC214  -  [R0402_0OHM]  141.25 79.25 90 top
RC215  -  [R_0402]  125.82 80.52 90 top
RC216  -  [R0603_0OHM]  93.37 133.55 180 top
RC217  -  [R_0402]  91.15 126.24 90 bottom
RC218  -  [R_0402]  92.04 125.37 270 bottom
RC219  -  [R_0402]  91.15 125.37 270 bottom
RC220  -  [R_0402]  125.8 78.75 0 top
RC221  -  [R0402_0OHM]  230.69 87.77 335 bottom
RC222  -  [R_0402]  226.85 80.98 225 bottom
RC223  -  [R_0402]  124.13 78.5 180 top
RC224  -  [R_0402]  149.96 113.68 180 bottom
RC225  -  [R_0402]  150.02 117.1 180 bottom
RC227  -  [R_0402]  150.89 117.1 0 bottom
RC228  -  [R0402_0OHM]  78.4 123.45 180 bottom
RC229  -  [R0402_0OHM]  80.67 119.78 270 bottom
RC230  -  [R0402_0OHM]  82.89 119.78 270 bottom
RC231  -  [R0402_0OHM]  109.55 97.52 0 top
RC234  -  [R_0402]  139.67 100.85 180 top
RC235  -  [R0402_0OHM]  137.88 99.95 90 top
RC237  -  [R_0402]  140.1 96.71 90 bottom
RC239  -  [R_0402]  97.24 127.13 90 bottom
RC240  -  [R_0402]  96.35 127.13 90 bottom
RC241  -  [R_0402]  91.35 127.2 180 top
RC243  -  [R_0402]  137.5 79.44 90 top
RC244  -  [R0402_0OHM]  157.81 120.34 0 bottom
RC267  -  [R_0402]  138.31 97.61 0 bottom
RC268  -  [R_0402]  137.25 97.62 270 bottom
RC272  -  [R_0402]  132.66 118.95 0 bottom
RC278  -  [R_0402]  141.9 98.94 180 bottom
RC279  -  [R_0402]  147.22 106.11 90 bottom
RC282  -  [R_0402]  145.05 85.61 0 top
RC283  -  [R_0402]  145.64 101.48 180 bottom
RC287  -  [R_0402]  134.33 102.49 90 top
RC288  -  [R_0402]  134.9 121.09 90 bottom
RC290  -  [R0402_0OHM]  151.74 113.68 180 bottom
RC291  -  [R_0402]  148.11 115.31 90 bottom
RC292  -  [R_0402]  139.08 98.94 0 bottom
RC295  -  [R0402_0OHM]  113.45 118.21 180 bottom
RC296  -  [R0402_0OHM]  132.94 82.62 180 top
RC297  -  [R_0402]  101.5 120.52 90 top
RC298  -  [R_0402]  100.61 120.52 90 top
RC299  -  [R0603_0OHM]  140.8 121.23 270 top
RC300  -  [R0402_0OHM]  128.93 120.23 270 bottom
RC301  -  [R0402_0OHM]  149.77 106.63 180 bottom
RC302  -  [R0402_0OHM]  127.66 121.44 270 top
RC303  -  [R0402_0OHM]  126.77 121.44 270 top
RC304  -  [R0402_0OHM]  132.4 100.57 180 top
RC305  -  [R0402_0OHM]  130.64 98.49 90 top
RC306  -  [R0402_0OHM]  138.02 102.82 180 top
RC307  -  [R0402_0OHM]  138.02 103.71 180 top
RC308  -  [R0402_0OHM]  138.02 104.6 180 top
RC309  -  [R0603_0OHM]  132.29 121.92 270 top
RC310  -  [R0603_0OHM]  131.02 121.92 270 top
RC311  -  [R_0402]  128.93 84.48 270 top
RC313  -  [R_0402]  139.04 101.8 180 bottom
RC316  -  [R_0402]  160.49 92.73 270 top
RC317  -  [R_0402]  139.22 97.98 90 top
RC318  -  [R_0402]  148.12 107.96 180 bottom
RC319  -  [R_0402]  150.4 111.07 180 bottom
RC323  -  [R_0402]  146.89 102.37 0 bottom
RC324  -  [R_0402]  108.34 110.07 270 top
RC325  -  [R0402_0OHM]  157.81 117.68 0 bottom
RC328  -  [R0402_0OHM]  96.59 118.88 0 bottom
RC330  -  [R_0402]  146 100.21 0 bottom
RC331  -  [R_0402]  146 99.32 0 bottom
RC337  -  [R0402_0OHM]  137.69 113.41 90 bottom
RC338  -  [R_0402]  136.8 113.41 90 bottom
RC344  -  [R_0402]  141.57 82.17 90 top
RC345  -  [R_0402]  135.61 108.28 180 bottom
RC346  -  [R_0402]  135.85 121.09 90 bottom
RC347  -  [R_0402]  142.57 101.48 0 bottom
RC348  -  [R_0402]  142.19 104.15 0 bottom
RC349  -  [R_0402]  137.95 82.7 270 top
RC362  -  [R_0402]  141.9 98.05 180 bottom
RC363  -  [R_0402]  141.9 97.17 180 bottom
RC366  -  [R_0402]  148.92 85.48 0 bottom
RC367  -  [R_0402]  148.92 87.26 0 bottom
RC368  -  [R_0402]  148.92 86.37 0 bottom
RC369  -  [R_0402]  148.92 88.15 0 bottom
RC371  -  [R_0402]  140.12 107.39 180 bottom
RC372  -  [R_0402]  140.12 108.28 180 bottom
RC373  -  [R0402_0OHM]  146.91 97.42 180 bottom
RC374  -  [R0402_0OHM]  146.91 96.53 180 bottom
RC375  -  [R0402_0OHM]  146.91 95.64 180 bottom
RC376  -  [R0402_0OHM]  139.74 84.47 180 top
RC377  -  [R0402_0OHM]  146.91 98.31 180 bottom
RC387  -  [R_0402]  142.45 84.86 270 top
RC400  -  [R_0402]  136.66 107.39 0 bottom
RC401  -  [R_0402]  136.66 108.28 0 bottom
RC402  -  [R_0402]  143.27 100.28 0 bottom
RC403  -  [R_0402]  143.27 99.39 0 bottom
RC405  -  [R_0402]  137.25 101.47 90 bottom
RC407  -  [R_0402]  155.85 97.92 90 top
RC408  -  [R_0402]  156.74 97.92 90 top
RC409  -  [R_0402]  157.63 97.92 90 top
RC410  -  [R_0402]  158.65 97.92 90 top
RC411  -  [R_0402]  122.82 81.8 0 top
RC413  -  [R_0402]  132.47 103.39 0 top
RC414  -  [R_0402]  135.72 84.48 270 top
RD4  -  [R_0402]  145.52 56.59 180 top
RD5  -  [R0402_0OHM]  143.36 56.59 180 top
RD6  -  [R_0402]  145.52 55.7 180 top
RD7  -  [R0402_0OHM]  143.36 55.7 180 top
RD8  -  [R_0402]  123.53 51.83 180 top
RD9  -  [R0402_0OHM]  122.62 52.72 0 top
RD10  -  [R0603_0OHM]  146.58 56.46 90 top
RD11  -  [R_0402]  103.58 53.48 0 top
RD12  -  [R0402_0OHM]  103.58 52.59 0 top
RD14  -  [R_0402]  109.76 53.22 180 top
RD15  -  [R_0402]  116.98 54.18 0 top
RD16  -  [R_0402]  118.76 52.4 0 top
RD17  -  [R_0402]  117.88 53.3 270 top
RD18  -  [R_0402]  116.1 53.3 270 top
RD19  -  [R_0402]  69.19 82.88 180 bottom
RE5  -  [R_0402]  248.05 97.22 90 top
RE6  -  [R_0402]  270.79 87.3 90 top
RE8  -  [R_0402]  256.63 96.07 90 top
RE10  -  [R_0402]  258.66 81.88 270 top
RE11  -  [R_0402]  247.04 80.92 270 top
RE12  -  [R_0402]  259.92 79.96 0 top
RE13  -  [R_0402]  266.2 88.15 0 top
RE14  -  [R_0402]  267.12 89.04 180 top
RE15  -  [R_0402]  266.2 87.26 0 top
RE16  -  [R_0402]  268.07 89.06 270 top
RE17  -  [R_0402]  269.92 88.15 90 top
RE18  -  [R_0402]  269 89.06 270 top
RE20  -  [R_0402]  247.99 80.92 270 top
RE21  -  [R_0402]  246.28 96.2 90 top
RE25  -  [R_0402]  259.28 96.98 0 top
RE26  -  [R_0402]  261.97 96.98 180 top
RE30  -  [R0402_0OHM]  288.36 121.36 0 bottom
RE31  -  [R_0402]  244.24 78.64 270 top
RE32  -  [R0402_0OHM]  244.24 79.5 90 top
RE33  -  [R_0402]  243.36 77.72 90 top
RE34  -  [R0402_0OHM]  244.45 95.39 180 top
RE35  -  [R_0402]  258.41 96.07 90 top
RE37  -  [R_0402]  260.79 82.17 270 top
RE38  -  [R_0402]  257.52 96.07 90 top
RE43  -  [R_0402]  259.55 81.88 270 top
RE48  -  [R_0402]  240.07 122.06 180 bottom
RE51  -  [R_0402]  240.07 121.17 180 bottom
RE55  -  [R_0402]  246.09 80.92 270 top
RE56  -  [R_0402]  236.03 84.62 90 top
RE57  -  [R_0402]  245.34 75.78 270 top
RE58  -  [R_0402]  246.09 77.72 90 top
RE59  -  [R0402_0OHM]  255.04 97.22 90 top
RE60  -  [R_0402]  253.64 95.76 90 top
RE63  -  [R_0402]  249.63 99.77 0 top
RE64  -  [R_0402]  255.99 79.91 270 top
RE65  -  [R_0402]  248.69 101.93 180 top
RE67  -  [R_0402]  236.02 83.7 90 bottom
RE68  -  [R_0402]  239.32 85.33 0 top
RE69  -  [R_0402]  267.94 100.98 180 top
RE70  -  [R_0402]  261.95 102.56 0 top
RE71  -  [R_0402]  288.24 127.07 0 bottom
RE72  -  [R_0402]  286.21 121.36 0 bottom
RE73  -  [R_0402]  286.21 122.31 0 bottom
RE74  -  [R_0402]  288.36 120.47 0 bottom
RE75  -  [R_0402]  286.21 123.26 0 bottom
RE77  -  [R_0402]  244.45 94.5 180 top
RE79  -  [R_0402]  250.39 102.82 0 top
RE83  -  [R_0402]  250.85 97.92 90 top
RE84  -  [R_0402]  250.99 101.94 180 top
RE85  -  [R_0402]  250.54 100.66 180 top
RE86  -  [R_0402]  288.36 123.26 0 bottom
RE90  -  [R0402_0OHM]  262.86 103.45 180 top
RE91  -  [R_0402]  249.96 97.92 90 top
RE92  -  [R_0402]  250.65 74.62 0 top
RE93  -  [R_0201]  245.6 99.9 0 top
RE94  -  [R_0402]  247.08 103.97 0 top
RE95  -  [R_0402]  260.79 92.12 0 top
RE98  -  [R_0402]  262.16 85.05 90 top
RE274  -  [R_0402]  259.93 78.17 90 top
RE275  -  [R0402_0OHM]  260.82 79.08 270 top
RE280  -  [R_0402]  262.16 99.07 180 top
RE288  -  [R_0402]  252.25 95.76 90 top
RE290  -  [R0402_0OHM]  244.5 84.86 270 top
RE292  -  [R_0402]  261.25 98.18 0 top
RE300  -  [R_0402]  256.82 97.85 90 top
RE301  -  [R_0402]  247.17 96.2 90 top
RE302  -  [R_0402]  241.15 87.13 180 top
RE303  -  [R_0402]  241.15 86.24 180 top
RE304  -  [R_0402]  267 100.02 180 top
RE306  -  [R_0402]  289.28 122.31 180 bottom
RE308  -  [R_0402]  262.33 100.4 180 top
RE312  -  [R_0402]  257.26 77.62 270 top
RE313  -  [R_0402]  256.87 78.62 0 top
RE314  -  [R_0402]  251.09 79.13 0 top
RE318  -  [R0402_0OHM]  249.52 75.78 270 top
RE324  -  [R_0402]  246.21 75.78 270 top
RE337  -  [R_0402]  255.99 76.71 90 top
RE338  -  [R_0402]  263.05 82.31 180 top
RE339  -  [R_0402]  260.68 83.13 180 top
RE340  -  [R_0402]  270.28 80.26 90 top
RE341  -  [R_0402]  258.79 78.17 90 top
RE342  -  [R_0402]  262.14 84.11 0 top
RE343  -  [R_0402]  249.72 77.73 180 top
RE348  -  [R_0402]  242.67 95.39 180 top
RE349  -  [R_0402]  263.05 83.2 180 top
RE350  -  [R_0402]  247.99 75.78 270 top
RE360  -  [R0402_0OHM]  262.14 81.42 0 top
RE361  -  [R_0402]  247.04 78.64 270 top
RE362  -  [R_0402]  247.93 78.64 270 top
RE363  -  [R_0402]  253.01 80.8 270 top
RE364  -  [R0402_0OHM]  259.76 84.11 0 top
RE365  -  [R_0402]  208.19 58.49 180 top
RE366  -  [R_0402]  253.07 104.81 90 top
RE367  -  [R_0402]  252.83 115.33 180 top
RE368  -  [R_0402]  253.96 104.81 90 top
RE369  -  [R_0402]  252.83 116.22 180 top
RE370  -  [R_0402]  255.81 103.9 90 top
RE371  -  [R_0402]  252.83 118.12 180 top
RE372  -  [R_0402]  254.93 103.9 90 top
RE373  -  [R_0402]  250.34 116.48 270 top
RE374  -  [R_0402]  252.06 104.01 90 top
RE375  -  [R_0402]  248.87 55.07 0 bottom
RE376  -  [R_0402]  255.81 105.67 90 top
RE377  -  [R_0402]  254.93 105.67 90 top
RE505  -  [R_0402]  254.23 127.84 180 bottom
RE507  -  [R_0402]  237.97 83.59 90 top
RE508  -  [R_0402]  237.97 86.55 270 top
RE512  -  [R_0402]  239.37 87.16 270 top
RE513  -  [R_0402]  241.15 88.12 180 top
RE514  -  [R_0402]  245.63 103.99 180 top
RE515  -  [R0402_0OHM]  245.63 104.93 180 top
RE524  -  [R_0402]  259.76 85.95 0 top
RE525  -  [R_0402]  259.76 85.06 0 top
RE526  -  [R_0402]  221.33 55.19 180 top
RE530  -  [R_0402]  237.35 129.75 0 bottom
RE532  -  [R_0402]  229.94 61.29 0 bottom
RE536  -  [R_0402]  242.94 107.26 0 top
RE537  -  [R_0402]  244.58 108.47 180 top
RE539  -  [R_0402]  257.61 99.63 90 top
RI13  -  [R_0402]  275.3 78.74 90 top
RI14  -  [R_0402]  280.58 76.53 180 top
RI27  -  [R_0402]  234.15 104.21 180 top
RI28  -  [R_0402]  234.15 105.1 180 top
RI29  -  [R_0402]  230.78 100.77 90 top
RI30  -  [R_0402]  229.89 100.77 90 top
RI47  -  [R_0402]  234.16 107.26 180 top
RI48  -  [R_0402]  234.16 106.37 180 top
RI49  -  [R_0402]  228.93 79.13 0 bottom
RI50  -  [R_0402]  228.93 78.24 0 bottom
RL1  -  [R_0402]  245.34 131.27 180 bottom
RL2  -  [R_0402]  243.22 130.25 0 bottom
RL3  -  [R0402_0OHM]  245.58 120.86 270 top
RL4  -  [R_0402]  241.84 123.2 180 top
RL5  -  [R_0402]  242.92 119.96 180 top
RL6  -  [R_0402]  241.13 120.86 270 top
RL7  -  [R0402_0OHM]  242.01 119.07 0 top
RL8  -  [R0603_0OHM]  241.7 125.04 180 bottom
RL9  -  [R_0402]  243.8 120.86 270 top
RL11  -  [R_0402]  248.3 120.34 0 top
RL12  -  [R_0402]  246.04 129.23 180 bottom
RL13  -  [R_0402]  250.34 121.36 270 top
RL14  -  [R_0402]  282.41 121.05 270 top
RL15  -  [R_0402]  270.15 119.15 90 top
RL16  -  [R_0402]  268.88 119.15 90 top
RL17  -  [R_0402]  262.53 119.14 90 top
RL18  -  [R_0402]  261.26 119.14 90 top
RL19  -  [R_0402]  281.46 121.05 270 top
RL20  -  [R_0402]  280.5 121.05 270 top
RL29  -  [R_0402]  255.23 132.21 90 top
RL30  -  [R_0402]  256.12 132.21 90 top
RL34  -  [R0402_0OHM]  246.52 120.34 0 top
RL70  -  [R_0402]  145.64 102.37 180 bottom
RL71  -  [R_0603]  252.18 121.99 0 top
RL72  -  [R_0603]  252.18 123.2 0 top
RL73  -  [R_0603]  252.18 124.41 0 top
RL74  -  [R_0603]  252.18 125.61 0 top
RL75  -  [R_0603]  251.93 126.82 0 top
RL76  -  [R_0603]  251.93 128.03 0 top
RL77  -  [R_0603]  251.8 129.23 0 top
RL78  -  [R_0603]  251.8 130.44 0 top
RN37  -  [R_0402]  23.9 46.04 90 top
RN99  -  [R0402_0OHM]  12.98 47.38 90 bottom
RN100  -  [R_0402]  25.17 51.18 90 top
RN101  -  [R_0402]  239.98 108.53 0 top
RPC1  -  [RP_0804_8P4R]  158.13 95.71 270 top
RPC3  -  [RP_0804_8P4R]  132.98 120.4 90 bottom
RPC4  -  [RP_0804_8P4R]  146.39 109.24 0 bottom
RPE7  -  [RP_0804_8P4R]  289.08 125.86 180 bottom
RPE9  -  [RP_0804_8P4R]  261.77 94.74 0 top
RPE10  -  [RP_0804_8P4R]  258.68 99.13 90 top
RPE11  -  [RP_0804_8P4R]  254.71 77.74 270 top
RPE12  -  [RP_0804_8P4R]  261.5 90.93 0 top
RR3  -  [R_0402]  273.76 69.53 270 top
RR4  -  [R_0402]  270.99 61.76 180 top
RR5  -  [R0402_0OHM]  278.74 59.9 270 top
RR6  -  [R0402_0OHM]  280.05 60.34 0 top
RR7  -  [R0402_0OHM]  280.05 61.22 0 top
RR8  -  [R0402_0OHM]  280.05 62.11 0 top
RR9  -  [R0402_0OHM]  276.82 61.17 270 top
RR10  -  [R0402_0OHM]  277.71 61.17 270 top
RR19  -  [R_0402]  272.85 68.62 90 top
RT50  -  [R_0402]  29.22 70.5 0 top
RT51  -  [R_0402]  27.98 69.54 180 top
RT52  -  [R_0402]  27.98 70.5 180 top
RT53  -  [R_0402]  27.98 72.4 180 top
RT54  -  [R0402_0OHM]  30.14 71.51 180 top
RT55  -  [R0402_0OHM]  30.14 72.4 180 top
RT56  -  [R0402_0OHM]  27.06 71.45 0 top
RT57  -  [R0402_0OHM]  27.06 68.59 0 top
RT58  -  [R0402_0OHM]  39.91 82.88 180 bottom
RT59  -  [R0402_0OHM]  39 79.39 0 bottom
RT60  -  [R0402_0OHM]  36.93 80.66 180 top
RT63  -  [R0402_0OHM]  32.41 86.23 90 top
RT64  -  [R_0402]  36.02 78.88 0 top
RT65  -  [R_0402]  36.02 77.99 0 top
RT66  -  [R_0402]  38.5 82.68 90 top
RT67  -  [R_0402]  37.62 82.68 90 top
RT68  -  [R_0402]  36.02 79.77 0 top
RT69  -  [R0402_0OHM]  36.61 85.23 180 top
RT70  -  [R0402_0OHM]  34.57 89.18 270 top
RT71  -  [R_0402]  33.74 78.48 90 bottom
RT72  -  [R0402_0OHM]  29.93 75.44 90 top
RT73  -  [R0402_0OHM]  30.9 78.75 0 bottom
RT74  -  [R_0402]  31.81 77.8 180 bottom
RT75  -  [R_0402]  29.5 74.18 180 top
RT76  -  [R_0402]  28.46 82.52 180 bottom
RT81  -  [R_0402]  32.22 86.8 90 bottom
RT82  -  [R_0402]  31.33 86.8 90 bottom
RT83  -  [R0402_0OHM]  31.32 85.93 0 bottom
RT84  -  [R_0402]  28.66 85.98 90 bottom
RT85  -  [R_0402]  28.87 84.4 180 bottom
RT86  -  [R_0402]  31.9 76.35 270 top
RT87  -  [R_0402]  23.57 81.23 0 top
RT88  -  [R_0402]  23.57 82.12 0 top
RT89  -  [R0402_0OHM]  25.22 83.01 0 top
RT90  -  [R0402_0OHM]  25.22 83.89 0 top
RT92  -  [R0402_0OHM]  25.42 85.81 270 top
RT93  -  [R0402_0OHM]  26.31 85.81 270 top
RT95  -  [R_0402]  28.1 87.26 180 top
RT96  -  [R_0402]  28.97 87.26 0 top
RT97  -  [R_0402]  31.66 73.29 180 top
RT98  -  [R_0402]  29.5 73.29 180 top
RT99  -  [R0402_0OHM]  30.75 74.18 0 top
RT100  -  [R_0402]  30.44 85.98 90 bottom
RT101  -  [R_0402]  32.23 81.35 180 bottom
RT103  -  [R_0402]  27.65 76.1 270 top
RT104  -  [R0402_0OHM]  26.83 78.56 180 top
RT105  -  [R0402_0OHM]  26.83 77.54 180 top
RT106  -  [R_0402]  29.55 85.98 90 bottom
RT107  -  [R_0402]  33.62 81.91 90 bottom
RT108  -  [R0402_0OHM]  26.83 79.58 180 top
RT109  -  [R0402_0OHM]  26.83 80.47 180 top
RT110  -  [R_0402]  30.88 75.44 90 top
RT111  -  [R_0402]  21.09 68.15 0 top
RT120  -  [R0402_0OHM]  15.59 107.14 180 top
RT121  -  [R0402_0OHM]  15.59 106.25 180 top
RT122  -  [R0402_0OHM]  14.68 107.14 0 bottom
RT123  -  [R0402_0OHM]  14.68 106.25 0 bottom
RT130  -  [R_0402]  28.21 109.23 0 top
RT131  -  [R_0402]  27.34 109.23 180 top
RT132  -  [R_0402]  25.36 110.11 90 top
RT133  -  [R_0402]  26.25 110.11 90 top
RT135  -  [R_0402]  27.84 99.15 270 bottom
RT136  -  [R_0402]  28.73 100.2 90 bottom
RT137  -  [R_0402]  31.95 102.37 0 bottom
RT138  -  [R_0402]  30.52 102.37 180 bottom
RT139  -  [R_0402]  31.95 103.71 0 bottom
RT140  -  [R_0402]  30.52 104.6 180 bottom
RT141  -  [R_0402]  25.11 104.77 90 bottom
RT142  -  [R_0402]  25.09 103.9 0 bottom
RT143  -  [R_0402]  24.15 101.24 270 bottom
RT144  -  [R_0402]  25.09 102.12 0 bottom
RT145  -  [R_0402]  31.95 105.61 0 bottom
RT246  -  [R0402_0OHM]  25.11 97.67 90 top
RT247  -  [R_0402]  26 98.58 270 bottom
RT248  -  [R_0402]  26 99.44 90 bottom
RT300  -  [R_0402]  30.52 105.48 180 bottom
RT301  -  [R_0402]  30.52 106.37 180 bottom
RT302  -  [R_0402]  30.52 101.48 180 bottom
RT303  -  [R_0402]  25.11 99.44 90 bottom
RT304  -  [R_0402]  25.09 101.23 0 bottom
RT305  -  [R_0402]  27.84 100.2 90 bottom
RT306  -  [R_0402]  30.52 103.71 180 bottom
RT307  -  [R_0402]  25.09 103.01 0 bottom
RT308  -  [R_0402]  24.41 107.95 90 top
RT339  -  [R_0402]  32.23 80.47 180 bottom
RT375  -  [R_0402]  25.42 88.23 270 top
RT376  -  [R_0402]  26.31 88.23 270 top
RT377  -  [R_0402]  29.3 81.34 90 bottom
RT378  -  [R_0402]  32.79 88.26 90 top
RT379  -  [R_0402]  33.68 88.26 90 top
RT380  -  [R0402_0OHM]  23.28 105.65 0 bottom
RT393  -  [R_0402]  21.09 69.05 0 top
RV1  -  [R_0402]  71.47 126.19 180 top
RV2  -  [R_0402]  72.24 122.31 180 top
RV3  -  [R_0402]  70.39 122.31 180 top
RV4  -  [R_0402]  43.08 123.72 270 top
RV5  -  [R_0402]  42.19 124.59 90 top
RV6  -  [R_0402]  50.32 121.03 90 top
RV7  -  [R_0402]  64.21 132.15 0 top
RV8  -  [R_0402]  66.06 133.41 90 top
RV10  -  [R_0402]  18.77 80.53 180 top
RV11  -  [R_0402]  18.77 81.42 180 top
RV12  -  [R_0402]  18.77 82.37 180 top
RV13  -  [R_0402]  18.77 83.26 180 top
